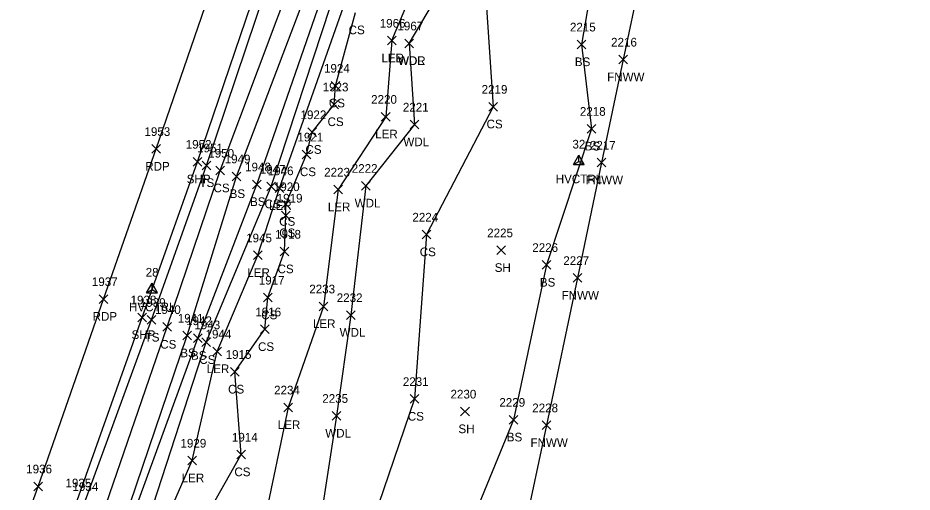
# Model space of a CAD drawing. Extents: x 1483143 to 1488182, y 802902 to 807581.
# Drawn here: x 1487923.3 to 1488129.5, y 806675.5 to 806784.9 of the extents above; entities that cross this region are included whole.
import ezdxf

# ---------------------------------------------------------------- set-up
doc = ezdxf.new("R2010")
doc.units = 0
for name, color, linetype in [('C_A', 7, 'Continuous'), ('C_I', 7, 'Continuous'), ('CPSM', 7, 'Continuous'), ('L_A', 7, 'Continuous'), ('L_I', 7, 'Continuous'), ('L_TIC', 7, 'Continuous'), ('LARO', 7, 'Continuous'), ('LAWA', 7, 'Continuous'), ('LELB', 7, 'Continuous'), ('LFNC', 7, 'Continuous'), ('P_A', 7, 'Continuous'), ('P_I', 7, 'Continuous'), ('P_TIC', 7, 'Continuous'), ('PET', 7, 'Continuous'), ('PSP', 7, 'Continuous')]:
    doc.layers.add(name, color=color, linetype=linetype)

msp = doc.modelspace()

# ---------------------------------------------------------------- linework, layer by layer
at = {"layer": 'CPSM'}
for p, q in [((1488051.38, 806751.02), (1488052.63, 806753.19)), ((1488053.88, 806751.02), (1488052.63, 806753.19)), ((1488052.63, 806751.74), (1488052.63, 806753.19)), ((1488051.38, 806751.02), (1488052.63, 806751.74)), ((1488051.38, 806751.02), (1488053.88, 806751.02)), ((1488052.63, 806751.74), (1488052.63, 806751.74)), ((1488052.63, 806751.74), (1488053.88, 806751.02)), ((1487953, 806721.47), (1487954.25, 806723.64)), ((1487955.5, 806721.47), (1487954.25, 806723.64)), ((1487954.25, 806722.19), (1487954.25, 806723.64)), ((1487953, 806721.47), (1487954.25, 806722.19)), ((1487953, 806721.47), (1487955.5, 806721.47)), ((1487954.25, 806722.19), (1487954.25, 806722.19)), ((1487954.25, 806722.19), (1487955.5, 806721.47))]:
    msp.add_line(p, q, dxfattribs=at)
at = {"layer": 'L_TIC'}
for points in [[(1488008.53, 806778.63), (1488010.53, 806780.63)], [(1488010.53, 806778.63), (1488008.53, 806780.63)], [(1488008.53, 806778.63), (1488010.53, 806780.63)], [(1488010.53, 806778.63), (1488008.53, 806780.63)], [(1488012.56, 806778), (1488014.56, 806780)], [(1488014.56, 806778), (1488012.56, 806780)], [(1488012.56, 806778), (1488014.56, 806780)], [(1488014.56, 806778), (1488012.56, 806780)], [(1488052.28, 806777.75), (1488054.28, 806779.75)], [(1488054.28, 806777.75), (1488052.28, 806779.75)], [(1488061.83, 806774.27), (1488063.83, 806776.27)], [(1488063.83, 806774.27), (1488061.83, 806776.27)], [(1487995.58, 806768.24), (1487997.58, 806770.24)], [(1487997.58, 806768.24), (1487995.58, 806770.24)], [(1487995.27, 806763.92), (1487997.27, 806765.92)], [(1487997.27, 806763.92), (1487995.27, 806765.92)], [(1488031.93, 806763.39), (1488033.93, 806765.39)], [(1488033.93, 806763.39), (1488031.93, 806765.39)], [(1488007.11, 806761.07), (1488009.11, 806763.07)], [(1488009.11, 806761.07), (1488007.11, 806763.07)], [(1488013.78, 806759.28), (1488015.78, 806761.28)], [(1488015.78, 806759.28), (1488013.78, 806761.28)], [(1488054.57, 806758.29), (1488056.57, 806760.29)], [(1488056.57, 806758.29), (1488054.57, 806760.29)], [(1487990.17, 806757.52), (1487992.17, 806759.52)], [(1487992.17, 806757.52), (1487990.17, 806759.52)], [(1487988.89, 806752.37), (1487990.89, 806754.37)], [(1487990.89, 806752.37), (1487988.89, 806754.37)], [(1488056.88, 806750.49), (1488058.88, 806752.49)], [(1488058.88, 806750.49), (1488056.88, 806752.49)], [(1487965.77, 806749.86), (1487967.77, 806751.86)], [(1487967.77, 806749.86), (1487965.77, 806751.86)], [(1487968.99, 806748.64), (1487970.99, 806750.64)], [(1487970.99, 806748.64), (1487968.99, 806750.64)], [(1487972.69, 806747.32), (1487974.69, 806749.32)], [(1487974.69, 806747.32), (1487972.69, 806749.32)], [(1487977.4, 806745.47), (1487979.4, 806747.47)], [(1487979.4, 806745.47), (1487977.4, 806747.47)], [(1487980.74, 806744.96), (1487982.74, 806746.96)], [(1487982.74, 806744.96), (1487980.74, 806746.96)], [(1487982.66, 806744.59), (1487984.66, 806746.59)], [(1487984.66, 806744.59), (1487982.66, 806746.59)], [(1487996.19, 806744.28), (1487998.19, 806746.28)], [(1487998.19, 806744.28), (1487996.19, 806746.28)], [(1488002.55, 806745.14), (1488004.55, 806747.14)], [(1488004.55, 806745.14), (1488002.55, 806747.14)], [(1487984.11, 806740.92), (1487986.11, 806742.92)], [(1487986.11, 806740.92), (1487984.11, 806742.92)], [(1487984.12, 806738.28), (1487986.12, 806740.28)], [(1487986.12, 806738.28), (1487984.12, 806740.28)], [(1488016.53, 806733.89), (1488018.53, 806735.89)], [(1488018.53, 806733.89), (1488016.53, 806735.89)], [(1487983.75, 806729.96), (1487985.75, 806731.96)], [(1487985.75, 806729.96), (1487983.75, 806731.96)], [(1488033.77, 806730.27), (1488035.77, 806732.27)], [(1488035.77, 806730.27), (1488033.77, 806732.27)], [(1487977.63, 806729.1), (1487979.63, 806731.1)], [(1487979.63, 806729.1), (1487977.63, 806731.1)], [(1488044.22, 806726.88), (1488046.22, 806728.88)], [(1488046.22, 806726.88), (1488044.22, 806728.88)], [(1488051.32, 806723.88), (1488053.32, 806725.88)], [(1488053.32, 806723.88), (1488051.32, 806725.88)], [(1487979.98, 806719.35), (1487981.98, 806721.35)], [(1487981.98, 806719.35), (1487979.98, 806721.35)], [(1487992.76, 806717.32), (1487994.76, 806719.32)], [(1487994.76, 806717.32), (1487992.76, 806719.32)], [(1487999.09, 806715.32), (1488001.09, 806717.32)], [(1488001.09, 806715.32), (1487999.09, 806717.32)], [(1487953.13, 806714.2), (1487955.13, 806716.2)], [(1487955.13, 806714.2), (1487953.13, 806716.2)], [(1487956.7, 806712.57), (1487958.7, 806714.57)], [(1487958.7, 806712.57), (1487956.7, 806714.57)], [(1487979.24, 806712.03), (1487981.24, 806714.03)], [(1487981.24, 806712.03), (1487979.24, 806714.03)], [(1487961.32, 806710.59), (1487963.32, 806712.59)], [(1487963.32, 806710.59), (1487961.32, 806712.59)], [(1487963.79, 806710), (1487965.79, 806712)], [(1487965.79, 806710), (1487963.79, 806712)], [(1487965.7, 806709.04), (1487967.7, 806711.04)], [(1487967.7, 806709.04), (1487965.7, 806711.04)], [(1487968.28, 806706.92), (1487970.28, 806708.92)], [(1487970.28, 806706.92), (1487968.28, 806708.92)], [(1487972.34, 806702.22), (1487974.34, 806704.22)], [(1487974.34, 806702.22), (1487972.34, 806704.22)], [(1488013.76, 806695.96), (1488015.76, 806697.96)], [(1488015.76, 806695.96), (1488013.76, 806697.96)], [(1487984.65, 806694.01), (1487986.65, 806696.01)], [(1487986.65, 806694.01), (1487984.65, 806696.01)], [(1488025.4, 806693.07), (1488027.4, 806695.07)], [(1488027.4, 806693.07), (1488025.4, 806695.07)], [(1487995.76, 806692.07), (1487997.76, 806694.07)], [(1487997.76, 806692.07), (1487995.76, 806694.07)], [(1488036.59, 806691.17), (1488038.59, 806693.17)], [(1488038.59, 806691.17), (1488036.59, 806693.17)], [(1488044.16, 806689.9), (1488046.16, 806691.9)], [(1488046.16, 806689.9), (1488044.16, 806691.9)], [(1487973.79, 806683.14), (1487975.79, 806685.14)], [(1487975.79, 806683.14), (1487973.79, 806685.14)], [(1487962.5, 806681.75), (1487964.5, 806683.75)], [(1487964.5, 806681.75), (1487962.5, 806683.75)]]:
    msp.add_lwpolyline(points, dxfattribs=at)
at = {"layer": 'LARO'}
for points in [[(1487955.83, 806665.17), (1487963.5, 806682.75), (1487969.28, 806707.92), (1487978.63, 806730.1), (1487983.66, 806745.59), (1488000.22, 806792.76), (1488006.47, 806809.98), (1488013.83, 806831.14), (1488030.79, 806884.72), (1488037.4, 806905.47), (1488041.65, 806915.63)], [(1488009.53, 806779.63), (1488017.34, 806798.44), (1488024.35, 806825.16), (1488030.27, 806842.58), (1488034.42, 806840.15), (1488044.44, 806838.57), (1488052.46, 806849.77), (1488052.91, 806865.31), (1488059.03, 806876.42), (1488051.8, 806880.66), (1488043.87, 806884.98), (1488046.69, 806896.67), (1488050.72, 806901.7), (1488054.57, 806915.09)], [(1488009.53, 806779.63), (1488008.11, 806762.07), (1487997.19, 806745.28), (1487993.76, 806718.32), (1487985.65, 806695.01), (1487979.99, 806668.22), (1487974.36, 806655.69), (1487966.68, 806636.04), (1487956.68, 806612.98), (1487949.83, 806572.43), (1487937.7, 806551.52), (1487937.93, 806549.12), (1487933.98, 806528.45), (1487931.33, 806504.22), (1487936.03, 806486.24), (1487936.87, 806458.71), (1487938.26, 806448.96), (1487936.18, 806429.85), (1487938.33, 806405.75), (1487927.08, 806402.62)]]:
    msp.add_lwpolyline(points, dxfattribs=at)
at = {"layer": 'LAWA'}
for points in [[(1488013.56, 806779), (1488023.53, 806795.87), (1488017.34, 806798.44), (1488028.03, 806824.76), (1488034.42, 806840.15), (1488042.03, 806848.24), (1488048.04, 806850.12), (1488046.95, 806871.27), (1488050.41, 806877.98), (1488051.8, 806880.66), (1488060.09, 806903.93), (1488066.6, 806927.09)], [(1488013.56, 806779), (1488014.78, 806760.28), (1488003.55, 806746.14), (1488000.09, 806716.32), (1487996.76, 806693.07), (1487992.04, 806662.06), (1487979.2, 806652.61), (1487971.73, 806641.22), (1487963.74, 806612.04), (1487955.87, 806570.61), (1487948.83, 806547.8), (1487940.57, 806527.46), (1487937.43, 806503.41), (1487936.03, 806486.24), (1487944.09, 806456.8), (1487943.56, 806449.98), (1487942.37, 806424.18), (1487942.13, 806400.96)]]:
    msp.add_lwpolyline(points, dxfattribs=at)
at = {"layer": 'LELB'}
for points in [[(1487827.52, 806379.6), (1487850.09, 806437.73), (1487867.87, 806481.84), (1487885.56, 806528.78), (1487894.77, 806554.11), (1487911.86, 806599.05), (1487925.11, 806635.03), (1487938.6, 806672.73), (1487954.13, 806715.2), (1487966.77, 806750.86), (1487982.82, 806798.37), (1488000.33, 806849.53), (1488013.76, 806891.57), (1488028.96, 806936.12), (1488043.22, 806981), (1488053.37, 807013.21), (1488065.46, 807054.1), (1488079.1, 807097.32), (1488091.92, 807141.06), (1488105.94, 807188.64)], [(1487831.61, 806378.23), (1487855.61, 806436.65), (1487873.41, 806477.14), (1487888.61, 806527.7), (1487900.29, 806552.66), (1487915.56, 806597.3), (1487929.53, 806633.53), (1487942.79, 806670.21), (1487957.7, 806713.57), (1487969.99, 806749.64), (1487987.61, 806796.79), (1487994.35, 806813.4), (1488006.31, 806847.85), (1488017.75, 806890.1), (1488033.51, 806934.67), (1488047.05, 806979.87), (1488058.1, 807011.89), (1488070.58, 807052.35), (1488082.44, 807096.83), (1488095.42, 807139.95), (1488114.02, 807186.94)], [(1487835.19, 806376.59), (1487859.78, 806434.97), (1487877.62, 806477.28), (1487892.57, 806526.23), (1487904.08, 806551.45), (1487919.68, 806595.15), (1487934.47, 806632.17), (1487947.69, 806668.31), (1487962.32, 806711.59), (1487973.69, 806748.32), (1487991.68, 806795.65), (1487997.75, 806809.49), (1487999.54, 806813.18), (1488009.67, 806846.56), (1488021.34, 806888.06), (1488037.67, 806932.78), (1488051.91, 806977.51), (1488062.67, 807010.29), (1488074.95, 807051.31), (1488088, 807095.72), (1488100.03, 807138.12), (1488122.67, 807183.2)], [(1487837.5, 806376), (1487863.45, 806433.38), (1487880.32, 806475.86), (1487894.61, 806525.53), (1487906.02, 806551.4), (1487922.48, 806594.15), (1487937, 806631.99), (1487949.11, 806668.02), (1487964.79, 806711), (1487978.4, 806746.47), (1487994.99, 806794.38), (1488000.35, 806808.82), (1488001.34, 806812.09), (1488011.23, 806845.63), (1488024.65, 806886.78), (1488040.19, 806931.5), (1488054.27, 806976.88), (1488065.68, 807009.57), (1488076.91, 807050.77), (1488090.18, 807095.37), (1488103.15, 807137.16), (1488127.49, 807179.54)], [(1487839.66, 806374.66), (1487865.87, 806433.14), (1487881.15, 806476.22), (1487897.55, 806523.91), (1487908.57, 806550.53), (1487926.89, 806591.97), (1487940.49, 806630.59), (1487952.54, 806666.3), (1487966.7, 806710.04), (1487981.74, 806745.96), (1487997.33, 806793.52), (1488011.64, 806832), (1488027.95, 806886.11), (1488041.92, 806927.39), (1488045.38, 806935.91), (1488056.2, 806975.87), (1488068.38, 807008.79), (1488080.46, 807050.29), (1488092.26, 807094.39), (1488105.79, 807135.26), (1488129.48, 807176.06)], [(1488039.63, 806814.37), (1488031.14, 806790.78), (1488032.93, 806764.39), (1488017.53, 806734.89), (1488014.76, 806696.96), (1488001.7, 806658.62), (1487995.09, 806633.92), (1487984.98, 806604.57), (1487980.48, 806572.93), (1487969.96, 806553.52), (1487953.46, 806540.54), (1487965.47, 806536.44), (1487984.45, 806521.74), (1488004.88, 806498.25)], [(1488057.62, 806804.31), (1488053.28, 806778.75), (1488055.57, 806759.29), (1488045.22, 806727.88), (1488037.59, 806692.17), (1488022.17, 806654.43), (1488019.2, 806624.46), (1488014.13, 806598.44), (1488002.07, 806550.47)], [(1487966.43, 806669.3), (1487974.79, 806684.14), (1487973.34, 806703.22), (1487980.24, 806713.03), (1487980.98, 806720.35), (1487984.75, 806730.96), (1487985.12, 806739.28), (1487985.11, 806741.92), (1487989.89, 806753.37), (1487991.17, 806758.52), (1487996.27, 806764.92), (1487996.58, 806769.24), (1488001.14, 806786.1)]]:
    msp.add_lwpolyline(points, dxfattribs=at)
at = {"layer": 'LFNC'}
msp.add_lwpolyline([(1488105.96, 806931.77), (1488093.97, 806892.24), (1488086.74, 806870.75), (1488078.76, 806844.27), (1488074.64, 806830.72), (1488062.83, 806775.27), (1488057.88, 806751.49), (1488052.32, 806724.88), (1488045.16, 806690.9), (1488036.14, 806648.33), (1488029.99, 806618.82), (1488025.33, 806595.98), (1488015.01, 806545.3), (1488004.88, 806498.25), (1488001.38, 806481.96), (1487997.71, 806465.14), (1487995.36, 806451.92), (1487987.25, 806418.51), (1487973.91, 806378.22)], dxfattribs=at)
at = {"layer": 'P_TIC'}
for points in [[(1487954.19, 806753.64), (1487956.19, 806755.64)], [(1487956.19, 806753.64), (1487954.19, 806755.64)], [(1487963.7, 806750.7), (1487965.7, 806752.7)], [(1487965.7, 806750.7), (1487963.7, 806752.7)], [(1487942.06, 806719.01), (1487944.06, 806721.01)], [(1487944.06, 806719.01), (1487942.06, 806721.01)], [(1487950.99, 806714.79), (1487952.99, 806716.79)], [(1487952.99, 806714.79), (1487950.99, 806716.79)], [(1487926.99, 806675.8), (1487928.99, 806677.8)], [(1487928.99, 806675.8), (1487926.99, 806677.8)]]:
    msp.add_lwpolyline(points, dxfattribs=at)
at = {"layer": 'PET'}
msp.add_lwpolyline([(1487817.05, 806384.04), (1487839.67, 806441.4), (1487857.48, 806486.15), (1487875.5, 806533.55), (1487884.95, 806558.16), (1487901.52, 806603.65), (1487914.56, 806639.6), (1487927.99, 806676.8), (1487943.06, 806720.01), (1487955.19, 806754.64), (1487971.37, 806801.63), (1487988.85, 806854.11), (1488002.85, 806896.07), (1488017.7, 806940.87), (1488031.56, 806984.9), (1488041.8, 807017.08), (1488054.37, 807058.25), (1488067.6, 807101.48), (1488080.81, 807144.82), (1488095.07, 807192.49)], dxfattribs=at)
at = {"layer": 'PSP'}
msp.add_lwpolyline([(1487825.55, 806380.21), (1487847.81, 806437.56), (1487866.19, 806483.39), (1487884.04, 806529.78), (1487893.44, 806554.46), (1487910.05, 806599.89), (1487923.16, 806635.65), (1487936.98, 806673.57), (1487951.99, 806715.79), (1487964.7, 806751.7), (1487980.81, 806798.97), (1487998.23, 806850.18), (1488012.19, 806892.24), (1488027.11, 806936.91), (1488041.21, 806981.53), (1488051.31, 807013.35), (1488064.14, 807054.93), (1488077.14, 807097.61), (1488090.36, 807141.77), (1488104.31, 807189.57)], dxfattribs=at)

# ---------------------------------------------------------------- texts
at = {"layer": 'C_A'}
for p in [(1488047.32, 806746.74), (1487948.94, 806717.19)]:
    msp.add_text('HVCTRL', height=2, dxfattribs=at).set_placement(p)
at = {"layer": 'C_I'}
for s, p in [('32', (1488051.16, 806754.74)), ('28', (1487952.78, 806725.19))]:
    msp.add_text(s, height=2, dxfattribs=at).set_placement(p)
at = {"layer": 'L_A'}
for s, p in [('CS', (1487999.58, 806781.1)), ('LER', (1488007.11, 806774.63)), ('LEL', (1488007.17, 806774.63)), ('WDR', (1488010.92, 806774)), ('WDL', (1488010.98, 806774)), ('BS', (1488051.72, 806773.75)), ('FNWW', (1488059.17, 806770.27)), ('CS', (1487995.02, 806764.24)), ('CS', (1487994.71, 806759.92)), ('CS', (1488031.37, 806759.39)), ('LER', (1488005.69, 806757.07)), ('WDL', (1488012.19, 806755.28)), ('BS', (1488054.01, 806754.29)), ('CS', (1487989.61, 806753.52)), ('CS', (1487988.34, 806748.37)), ('TS', (1487965.18, 806745.86)), ('FNWW', (1488054.23, 806746.49)), ('CS', (1487968.43, 806744.64)), ('BS', (1487972.13, 806743.32)), ('BS', (1487976.84, 806741.47)), ('CS', (1487980.18, 806740.96)), ('LER', (1487981.24, 806740.59)), ('LER', (1487994.77, 806740.28)), ('WDL', (1488000.97, 806741.14)), ('CS', (1487983.55, 806736.92)), ('CS', (1487983.56, 806734.28)), ('CS', (1488015.97, 806729.89)), ('CS', (1487983.19, 806725.96)), ('SH', (1488033.25, 806726.27)), ('LER', (1487976.21, 806725.1)), ('BS', (1488043.66, 806722.88)), ('FNWW', (1488048.67, 806719.88)), ('CS', (1487979.43, 806715.35)), ('LER', (1487991.34, 806713.32)), ('WDL', (1487997.5, 806711.32)), ('TS', (1487952.54, 806710.2)), ('CS', (1487956.14, 806708.57)), ('BS', (1487960.76, 806706.59)), ('CS', (1487978.68, 806708.03)), ('BS', (1487963.23, 806706)), ('CS', (1487965.15, 806705.04)), ('LER', (1487966.86, 806702.92)), ('CS', (1487971.78, 806698.22)), ('CS', (1488013.21, 806691.96)), ('LER', (1487983.23, 806690.01)), ('WDL', (1487994.18, 806688.07)), ('SH', (1488024.89, 806689.07)), ('BS', (1488036.03, 806687.17)), ('FNWW', (1488041.5, 806685.9)), ('LER', (1487961.08, 806677.75)), ('CS', (1487973.23, 806679.14))]:
    msp.add_text(s, height=2, dxfattribs=at).set_placement(p)
at = {"layer": 'L_I'}
for s, p in [('1966', (1488006.74, 806782.63)), ('1966', (1488006.74, 806782.63)), ('1967', (1488010.82, 806782)), ('1967', (1488010.82, 806782)), ('2215', (1488050.59, 806781.75)), ('2216', (1488060.08, 806778.27)), ('1924', (1487993.89, 806772.24)), ('1923', (1487993.58, 806767.92)), ('2219', (1488030.23, 806767.39)), ('2220', (1488004.76, 806765.07)), ('2221', (1488012.08, 806763.28)), ('2218', (1488052.88, 806762.29)), ('1922', (1487988.48, 806761.52)), ('1921', (1487987.77, 806756.37)), ('2217', (1488055.19, 806754.49)), ('1951', (1487964.64, 806753.86)), ('1950', (1487967.21, 806752.64)), ('1949', (1487970.99, 806751.32)), ('1948', (1487975.7, 806749.47)), ('1947', (1487979.05, 806748.96)), ('1946', (1487980.91, 806748.59)), ('2223', (1487993.93, 806748.28)), ('2222', (1488000.29, 806749.14)), ('1920', (1487982.33, 806744.92)), ('1919', (1487982.99, 806742.28)), ('2224', (1488014.27, 806737.89)), ('1918', (1487982.63, 806733.96)), ('2225', (1488031.51, 806734.27)), ('1945', (1487975.94, 806733.1)), ('2226', (1488041.91, 806730.88)), ('2227', (1488049.06, 806727.88)), ('1917', (1487978.86, 806723.35)), ('2233', (1487990.5, 806721.32)), ('2232', (1487996.83, 806719.32)), ('1939', (1487951.43, 806718.2)), ('1940', (1487954.92, 806716.57)), ('1916', (1487978.06, 806716.03)), ('1941', (1487960.19, 806714.59)), ('1942', (1487962.1, 806714)), ('1943', (1487964.01, 806713.04)), ('1944', (1487966.58, 806710.92)), ('1915', (1487971.22, 806706.22)), ('2231', (1488012.07, 806699.96)), ('2234', (1487982.39, 806698.01)), ('2230', (1488023.06, 806697.07)), ('2235', (1487993.5, 806696.07)), ('2229', (1488034.32, 806695.17)), ('2228', (1488041.9, 806693.9)), ('1914', (1487972.66, 806687.14)), ('1929', (1487960.8, 806685.75)), ('1934', (1487935.91, 806675.73))]:
    msp.add_text(s, height=2, dxfattribs=at).set_placement(p)
at = {"layer": 'P_A'}
for s, p in [('RDP', (1487952.68, 806749.64)), ('SHP', (1487962.24, 806746.7)), ('RDP', (1487940.55, 806715.01)), ('SHP', (1487949.52, 806710.79))]:
    msp.add_text(s, height=2, dxfattribs=at).set_placement(p)
at = {"layer": 'P_I'}
for s, p in [('1953', (1487952.5, 806757.64)), ('1952', (1487962.01, 806754.7)), ('1937', (1487940.37, 806723.01)), ('1938', (1487949.3, 806718.79)), ('1936', (1487925.24, 806679.8)), ('1935', (1487934.29, 806676.57))]:
    msp.add_text(s, height=2, dxfattribs=at).set_placement(p)

doc.saveas('drawing.dxf')
